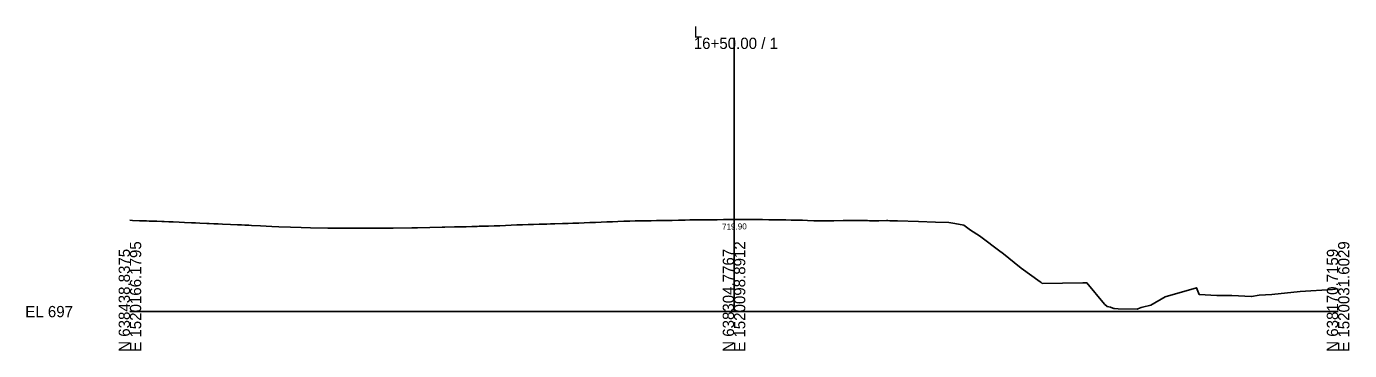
# Model space of a CAD drawing. Extents: x -26 to 3903, y -10 to 9531.
# Drawn here: x -25.7 to 302.8, y 6490.3 to 6570.9 of the extents above; entities that cross this region are included whole.
import ezdxf

# ---------------------------------------------------------------- set-up
doc = ezdxf.new("R2010")
doc.units = 0
for name, color, linetype in [('Default', 7, 'Continuous'), ('Exist Cross Section Cell', 7, 'Continuous'), ('Exist XS Center Line Elevation Label', 7, 'Continuous'), ('Exist XS Ground Line', 7, 'Continuous')]:
    doc.layers.add(name, color=color, linetype=linetype)

msp = doc.modelspace()

# ---------------------------------------------------------------- linework, layer by layer
at = {"layer": 'Exist Cross Section Cell'}
for p, q in [((150, 6500), (150, 6568.12)), ((0, 6500), (150, 6500)), ((150, 6500), (300, 6500))]:
    msp.add_line(p, q, dxfattribs=at)
at = {"layer": 'Exist XS Ground Line'}
msp.add_lwpolyline([(0, 6522.71), (0.62, 6522.68), (2.35, 6522.61), (2.67, 6522.6), (3.62, 6522.57), (4.09, 6522.54), (4.79, 6522.52), (5.14, 6522.5), (5.56, 6522.5), (5.62, 6522.5), (6.64, 6522.46), (7.92, 6522.4), (8.51, 6522.37), (9.7, 6522.33), (10.17, 6522.31), (10.72, 6522.29), (12.24, 6522.22), (13.52, 6522.16), (15.28, 6522.09), (15.97, 6522.07), (16.31, 6522.05), (17.37, 6522.01), (19.12, 6521.93), (19.68, 6521.9), (20.84, 6521.85), (21.55, 6521.82), (21.9, 6521.8), (22.98, 6521.76), (24.94, 6521.68), (26.7, 6521.6), (27.04, 6521.59), (27.2, 6521.58), (27.62, 6521.56), (27.73, 6521.55), (28.55, 6521.51), (29.53, 6521.46), (30.19, 6521.42), (32.4, 6521.32), (35.22, 6521.18), (36.97, 6521.12), (39.89, 6521), (42.56, 6520.91), (44.87, 6520.85), (49.11, 6520.77), (51.18, 6520.74), (53.58, 6520.71), (57.89, 6520.75), (60.41, 6520.73), (63.82, 6520.77), (65.39, 6520.77), (69.99, 6520.85), (71.42, 6520.87), (77.54, 6521.02), (77.58, 6521.02), (77.7, 6521.02), (78.17, 6521.03), (80.61, 6521.06), (81.17, 6521.07), (82.12, 6521.08), (83.45, 6521.11), (84.86, 6521.15), (86.26, 6521.2), (86.74, 6521.21), (87.69, 6521.24), (89.06, 6521.28), (90.47, 6521.33), (91.85, 6521.37), (93.29, 6521.42), (94.64, 6521.48), (96.05, 6521.54), (97.46, 6521.58), (98.86, 6521.63), (100.24, 6521.67), (101.64, 6521.72), (103.04, 6521.76), (103.51, 6521.77), (104.45, 6521.79), (105.54, 6521.83), (107.43, 6521.89), (107.57, 6521.89), (107.88, 6521.9), (108.82, 6521.93), (110.01, 6521.97), (111.44, 6522.03), (112.82, 6522.09), (114.23, 6522.15), (115.57, 6522.2), (117.03, 6522.24), (118.4, 6522.3), (119.83, 6522.36), (121.12, 6522.41), (122.62, 6522.46), (124.16, 6522.5), (125.42, 6522.54), (126.67, 6522.58), (128.22, 6522.61), (129.41, 6522.61), (130.74, 6522.63), (131.06, 6522.63), (131.15, 6522.64), (132.73, 6522.65), (133.45, 6522.66), (134.61, 6522.69), (136.25, 6522.74), (137.86, 6522.77), (139.04, 6522.79), (140.22, 6522.8), (141.82, 6522.81), (143.42, 6522.84), (144.61, 6522.85), (145.83, 6522.86), (147.4, 6522.88), (148.65, 6522.89), (149.73, 6522.91), (149.89, 6522.9), (150.21, 6522.9), (151.73, 6522.91), (153.03, 6522.91), (154.58, 6522.91), (155.82, 6522.89), (157.08, 6522.88), (158.61, 6522.86), (159.83, 6522.85), (160.75, 6522.84), (161.05, 6522.83), (161.39, 6522.82), (162.83, 6522.8), (164.19, 6522.77), (165.7, 6522.74), (166.55, 6522.71), (166.98, 6522.7), (168.28, 6522.65), (169.79, 6522.6), (171.28, 6522.57), (172.48, 6522.57), (173.8, 6522.6), (173.87, 6522.6), (174.4, 6522.61), (174.78, 6522.61), (177.09, 6522.62), (177.38, 6522.62), (177.55, 6522.62), (179.23, 6522.63), (180.35, 6522.63), (181.09, 6522.63), (182.61, 6522.62), (182.96, 6522.62), (183.14, 6522.62), (183.68, 6522.61), (185.94, 6522.61), (187.83, 6522.62), (188.06, 6522.62), (188.23, 6522.62), (188.68, 6522.6), (189.86, 6522.6), (190.23, 6522.6), (190.61, 6522.6), (195.78, 6522.4), (200, 6522.23), (203.33, 6522.16), (204.85, 6521.87), (207.1, 6521.51), (208.74, 6520.24), (210.97, 6518.84), (216.35, 6514.8), (216.4, 6514.76), (216.48, 6514.69), (221.27, 6510.8), (226.02, 6507.38), (226.26, 6507.21), (226.45, 6507.05), (226.5, 6507.02), (236.63, 6507.18), (237.61, 6507.14), (242.01, 6501.83), (242.64, 6501.28), (243.51, 6501.11), (243.66, 6501.02), (244.32, 6500.77), (244.46, 6500.74), (245.4, 6500.71), (250.11, 6500.63), (250.25, 6500.7), (251.11, 6500.98), (251.45, 6501.1), (253.5, 6501.61), (257.03, 6503.65), (264.87, 6505.92), (265.54, 6504.25), (269.85, 6504.01), (270.4, 6503.99), (270.7, 6503.99), (271.6, 6503.98), (273.62, 6504), (278.53, 6503.75), (280.41, 6504.07), (283.52, 6504.23), (290.61, 6504.99), (298.6, 6505.52), (300, 6505.63)], dxfattribs=at)

# ---------------------------------------------------------------- texts
at = {"layer": 'Default'}
msp.add_text('-', height=0.0001, dxfattribs=at).set_placement((0, 6500))
at = {"layer": 'Exist Cross Section Cell'}
for s, p in [('L', (140, 6568.12)), ('16+50.00 / 1', (140, 6565.32)), ('EL 697', (-26, 6498.6))]:
    msp.add_text(s, height=2.8, dxfattribs=at).set_placement(p)
for s, p in [('N 638438.8375', (0, 6490)), ('E 1520166.1795', (2.8, 6490)), ('N 638304.7767', (150, 6490)), ('E 1520098.8912', (152.8, 6490)), ('N 638170.7159', (300, 6490)), ('E 1520031.6029', (302.8, 6490))]:
    msp.add_text(s, height=2.8, rotation=90, dxfattribs=at).set_placement(p)
at = {"layer": 'Exist XS Center Line Elevation Label'}
msp.add_text('719.90', height=1.5, rotation=0.8401, dxfattribs=at).set_placement((147.04, 6520.36))

doc.saveas('drawing.dxf')
